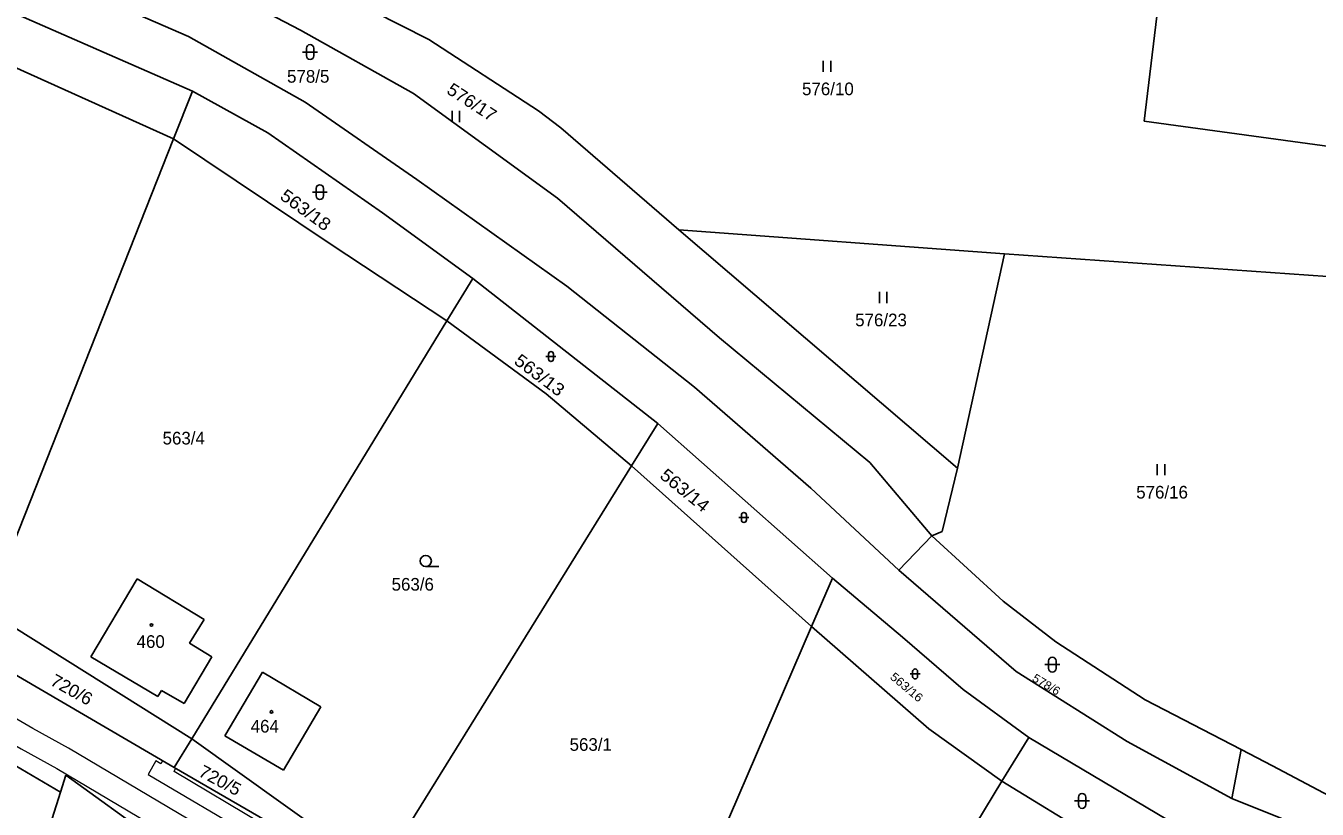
# Model space of a CAD drawing. Extents: x -701211 to -698780, y -1014269 to -1012378.
# Drawn here: x -700475.1 to -700301.5, y -1013234 to -1013128.7 of the extents above; entities that cross this region are included whole.
import ezdxf
from ezdxf.enums import TextEntityAlignment as Align

# ---------------------------------------------------------------- set-up
doc = ezdxf.new("R2010")
doc.units = 0
doc.header["$LTSCALE"] = 0.68
for name, color, linetype, lineweight in [('1', 7, 'Continuous', 25), ('13', 7, 'Continuous', 13), ('3', 7, 'Continuous', 25), ('5', 7, 'Continuous', 25)]:
    doc.layers.add(name, color=color, linetype=linetype, lineweight=lineweight)
doc.layers.add('2', color=7, linetype='Continuous')

msp = doc.modelspace()

# ---------------------------------------------------------------- linework, layer by layer
at = {"layer": '1'}
for p, q in [((-700324.78, -1013141.51), (-700320.68, -1013107.77)), ((-700420.91, -1013130.53), (-700449.41, -1013115.87)), ((-700438.17, -1013129.27), (-700459.72, -1013117.93)), ((-700453.22, -1013130.1), (-700475.81, -1013120.25)), ((-700483.31, -1013124.06), (-700452.68, -1013137.47)), ((-700455.23, -1013143.86), (-700491.3, -1013127.59)), ((-700422.97, -1013137.79), (-700438.17, -1013129.27)), ((-700437.51, -1013138.95), (-700453.22, -1013130.1)), ((-700406.15, -1013140.09), (-700420.91, -1013130.53)), ((-700452.68, -1013137.47), (-700455.23, -1013143.86)), ((-700452.68, -1013137.47), (-700442.56, -1013143.08)), ((-700403.62, -1013151.83), (-700422.97, -1013137.79)), ((-700422.52, -1013149.34), (-700437.51, -1013138.95)), ((-700403.16, -1013142.41), (-700406.15, -1013140.09)), ((-700324.78, -1013141.51), (-700288.22, -1013146.5)), ((-700442.56, -1013143.08), (-700427.12, -1013153.83)), ((-700387.3, -1013156.11), (-700403.16, -1013142.41)), ((-700480.3, -1013207.29), (-700455.23, -1013143.86)), ((-700455.23, -1013143.86), (-700434.17, -1013157.98)), ((-700402.38, -1013163.7), (-700422.52, -1013149.34)), ((-700381.83, -1013170.63), (-700403.62, -1013151.83)), ((-700427.12, -1013153.83), (-700415, -1013162.64)), ((-700343.52, -1013159.34), (-700387.3, -1013156.11)), ((-700387.3, -1013156.11), (-700349.87, -1013188.13)), ((-700434.17, -1013157.98), (-700418.5, -1013168.35)), ((-700343.52, -1013159.34), (-700349.87, -1013188.13)), ((-700290.05, -1013163.11), (-700343.52, -1013159.34)), ((-700415, -1013162.64), (-700418.5, -1013168.35)), ((-700415, -1013162.64), (-700390.12, -1013182.16)), ((-700385.22, -1013177.25), (-700402.38, -1013163.7)), ((-700418.5, -1013168.35), (-700452.75, -1013224.55)), ((-700405.13, -1013178.15), (-700418.5, -1013168.35)), ((-700361.64, -1013187.38), (-700381.83, -1013170.63)), ((-700393.67, -1013187.86), (-700405.13, -1013178.15)), ((-700369.56, -1013190.82), (-700385.22, -1013177.25)), ((-700390.12, -1013182.16), (-700393.67, -1013187.86)), ((-700366.66, -1013202.92), (-700390.12, -1013182.16)), ((-700427.55, -1013242.53), (-700393.67, -1013187.86)), ((-700369.46, -1013209.43), (-700393.67, -1013187.86)), ((-700353.32, -1013197.26), (-700361.64, -1013187.38)), ((-700351.91, -1013196.68), (-700349.87, -1013188.13)), ((-700357.76, -1013201.87), (-700369.56, -1013190.82)), ((-700353.32, -1013197.26), (-700357.76, -1013201.87)), ((-700351.91, -1013196.68), (-700353.32, -1013197.26)), ((-700353.32, -1013197.26), (-700343.72, -1013206.03)), ((-700357.76, -1013201.87), (-700341.97, -1013215.49)), ((-700466.32, -1013213.5), (-700460.09, -1013203.05)), ((-700460.09, -1013203.05), (-700451.12, -1013208.49)), ((-700369.46, -1013209.43), (-700366.66, -1013202.92)), ((-700357.23, -1013210.89), (-700366.66, -1013202.92)), ((-700343.72, -1013206.03), (-700336.65, -1013211.52)), ((-700452.75, -1013224.55), (-700480.3, -1013207.29)), ((-700369.46, -1013209.43), (-700393.34, -1013264.83)), ((-700353.71, -1013223.18), (-700369.46, -1013209.43)), ((-700349.1, -1013217.93), (-700357.23, -1013210.89)), ((-700455.12, -1013228.41), (-700482.34, -1013212.52)), ((-700336.65, -1013211.52), (-700324.62, -1013219.28)), ((-700457.33, -1013218.87), (-700466.32, -1013213.5)), ((-700450.06, -1013213.53), (-700453.8, -1013219.79)), ((-700448.32, -1013224.12), (-700443.28, -1013215.6)), ((-700443.28, -1013215.6), (-700435.4, -1013220.26)), ((-700341.97, -1013215.49), (-700327.07, -1013224.89)), ((-700456.81, -1013218.04), (-700457.33, -1013218.87)), ((-700453.8, -1013219.79), (-700456.81, -1013218.04)), ((-700340.25, -1013224.35), (-700349.1, -1013217.93)), ((-700324.62, -1013219.28), (-700311.72, -1013225.98)), ((-700435.4, -1013220.26), (-700440.44, -1013228.77)), ((-700343.9, -1013230.25), (-700353.71, -1013223.18)), ((-700455.12, -1013228.41), (-700452.75, -1013224.55)), ((-700427.55, -1013242.53), (-700452.75, -1013224.55)), ((-700440.44, -1013228.77), (-700448.32, -1013224.12)), ((-700343.9, -1013230.25), (-700340.25, -1013224.35)), ((-700320.2, -1013236.27), (-700340.25, -1013224.35)), ((-700327.07, -1013224.89), (-700312.97, -1013232.56)), ((-700312.97, -1013232.56), (-700311.72, -1013225.98)), ((-700311.72, -1013225.98), (-700307.52, -1013228.16)), ((-700470.4, -1013231.7), (-700477.27, -1013227.7)), ((-700455.12, -1013228.41), (-700428.37, -1013243.85)), ((-700307.52, -1013228.16), (-700299.91, -1013232.2)), ((-700470.4, -1013231.7), (-700469.69, -1013229.44)), ((-700448.91, -1013244.39), (-700469.69, -1013229.44)), ((-700359.38, -1013255.74), (-700343.9, -1013230.25)), ((-700323.64, -1013242.58), (-700343.9, -1013230.25)), ((-700475.28, -1013247.23), (-700470.4, -1013231.7)), ((-700312.97, -1013232.56), (-700298.98, -1013238.16))]:
    msp.add_line(p, q, dxfattribs=at)
msp.add_lwpolyline([(-700451.12, -1013208.49), (-700453.06, -1013211.66), (-700450.06, -1013213.53)], dxfattribs=at)
at = {"layer": '13'}
for points in [[(-700287.36, -1013363.02), (-700322.83, -1013322.02), (-700397.37, -1013268.79), (-700422.31, -1013253.72), (-700469.35, -1013225.78), (-700474.13, -1013223.15), (-700505.21, -1013205.06), (-700510.59, -1013202.27), (-700527.33, -1013194.88), (-700555.49, -1013183.11), (-700559.92, -1013181.38), (-700563.23, -1013179.64), (-700564.89, -1013177.43), (-700602.93, -1013162.92), (-700645.95, -1013152.22), (-700656.81, -1013151.49), (-700669.27, -1013150.25), (-700710.28, -1013153.93)], [(-700710.03, -1013157.08), (-700669.29, -1013153.42), (-700657.08, -1013154.63), (-700646.44, -1013155.36), (-700603.88, -1013165.94), (-700566.87, -1013180.06), (-700565.33, -1013182.09), (-700561.6, -1013184.11), (-700556.67, -1013186.04), (-700528.57, -1013197.79), (-700511.95, -1013205.13), (-700506.73, -1013207.83), (-700475.69, -1013225.9), (-700470.91, -1013228.52), (-700423.94, -1013256.43), (-700399.11, -1013271.43), (-700324.98, -1013324.37), (-700289.83, -1013365.01)]]:
    msp.add_lwpolyline(points, dxfattribs=at)
msp.add_lwpolyline([(-700456.7, -1013227.49), (-700456.91, -1013227.91), (-700457.59, -1013227.52), (-700458.63, -1013229.32), (-700444.35, -1013237.77), (-700442.85, -1013238.77), (-700443.98, -1013240.87), (-700442.15, -1013241.85), (-700440.06, -1013238.11), (-700443.25, -1013236.01), (-700455.15, -1013228.94), (-700454.93, -1013228.52), (-700455.12, -1013228.41)], close=True, dxfattribs=at)
at = {"layer": '3'}
for p, q in [((-700437.861, -1013132.201), (-700435.859, -1013132.201)), ((-700437.361, -1013131.701), (-700437.361, -1013132.702)), ((-700436.359, -1013132.702), (-700436.359, -1013131.701)), ((-700367.901, -1013134.88), (-700367.901, -1013133.38)), ((-700366.9, -1013134.88), (-700366.9, -1013133.38)), ((-700417.781, -1013141.62), (-700417.781, -1013140.12)), ((-700416.78, -1013141.62), (-700416.78, -1013140.12)), ((-700436.561, -1013151.041), (-700434.559, -1013151.041)), ((-700436.061, -1013150.541), (-700436.061, -1013151.542)), ((-700435.059, -1013151.542), (-700435.059, -1013150.541)), ((-700360.341, -1013165.95), (-700360.341, -1013164.45)), ((-700359.34, -1013165.95), (-700359.34, -1013164.45)), ((-700404.825, -1013172.805), (-700404.825, -1013173.476)), ((-700404.155, -1013173.476), (-700404.155, -1013172.805)), ((-700405.161, -1013173.141), (-700403.819, -1013173.141)), ((-700323.011, -1013189.11), (-700323.011, -1013187.61)), ((-700322.01, -1013189.11), (-700322.01, -1013187.61)), ((-700379.231, -1013194.781), (-700377.889, -1013194.781)), ((-700378.895, -1013194.445), (-700378.895, -1013195.116)), ((-700378.225, -1013195.116), (-700378.225, -1013194.445)), ((-700421.313, -1013201.38), (-700419.563, -1013201.38)), ((-700338.111, -1013214.571), (-700336.109, -1013214.571)), ((-700337.611, -1013214.071), (-700337.611, -1013215.072)), ((-700336.609, -1013215.072), (-700336.609, -1013214.071)), ((-700356.221, -1013215.821), (-700354.879, -1013215.821)), ((-700355.885, -1013215.485), (-700355.885, -1013216.156)), ((-700355.215, -1013216.156), (-700355.215, -1013215.485)), ((-700334.111, -1013232.891), (-700332.109, -1013232.891)), ((-700333.611, -1013232.391), (-700333.611, -1013233.392)), ((-700332.609, -1013233.392), (-700332.609, -1013232.391))]:
    msp.add_line(p, q, dxfattribs=at)
msp.add_circle((-700421.3129, -1013200.6298), 0.75, dxfattribs=at)
for centre, radius, start, end in [((-700436.86, -1013131.7009), 0.5, 0, 180), ((-700436.86, -1013132.7009), 0.5, 180, 359.98789), ((-700435.56, -1013150.5409), 0.5, 0, 180), ((-700435.56, -1013151.5409), 0.5, 180, 359.98789), ((-700404.49, -1013172.8056), 0.335, 0, 180), ((-700404.49, -1013173.4756), 0.335, 180, 359.98789), ((-700378.56, -1013194.4456), 0.335, 0, 180), ((-700378.56, -1013195.1156), 0.335, 180, 359.98789), ((-700337.11, -1013214.0709), 0.5, 0, 180), ((-700355.55, -1013215.4856), 0.335, 0, 180), ((-700355.55, -1013216.1556), 0.335, 180, 359.98789), ((-700337.11, -1013215.0709), 0.5, 180, 359.98789), ((-700333.11, -1013232.3909), 0.5, 0, 180), ((-700333.11, -1013233.3909), 0.5, 180, 359.98789)]:
    msp.add_arc(centre, radius, start, end, dxfattribs=at)
at = {"layer": '5'}
for centre in [(-700458.1668, -1013209.2392), (-700442.0468, -1013220.9292)]:
    msp.add_circle(centre, 0.175, dxfattribs=at)

# ---------------------------------------------------------------- texts
at = {"layer": '2'}
for s, p in [('578/5', (-700439.96, -1013136.325)), ('576/10', (-700370.75, -1013138.005)), ('576/23', (-700363.61, -1013169.075)), ('563/4', (-700456.69, -1013184.965)), ('576/16', (-700325.84, -1013192.235)), ('563/6', (-700425.91, -1013204.615)), ('460', (-700460.18, -1013212.315)), ('464', (-700444.85, -1013223.695)), ('563/1', (-700401.99, -1013226.155))]:
    msp.add_text(s, height=1.7, dxfattribs=at).set_placement(p)
for s, rotation, width, p in [('576/17', 327, 1.05, (-700418.641, -1013137.666)), ('563/13', 323, 1.1, (-700409.585, -1013174.009)), ('720/6', 331, 1.05, (-700471.926, -1013217.221)), ('720/5', 332, 1.05, (-700451.989, -1013229.465))]:
    msp.add_text(s, height=1.7, rotation=rotation, dxfattribs=dict(at, width=width)).set_placement(p)
for s, height, rotation, width, p in [('563/18', 1.7, 324, 1.1, (-700437.9551, -1013154.1184)), ('563/14', 1.7, 321, 1.1, (-700387.0249, -1013191.7799)), ('563/16', 1.14, 320, 1.1, (-700357.0559, -1013218.0346)), ('578/6', 1.14, 329, 1.05, (-700338.2066, -1013217.7332))]:
    msp.add_text(s, height=height, rotation=rotation, dxfattribs=dict(at, width=width)).set_placement(p, align=Align.CENTER)

doc.saveas('drawing.dxf')
